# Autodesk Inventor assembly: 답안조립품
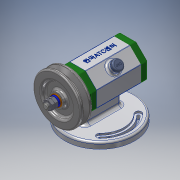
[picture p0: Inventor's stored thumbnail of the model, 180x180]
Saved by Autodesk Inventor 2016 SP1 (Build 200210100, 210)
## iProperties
Created: 2017-06
Part Number: 답안조립품
Material: 일반
Document SubType Name: Assembly
Designer: basic
Author: basic
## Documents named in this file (14)
- C:\Users\basic\Desktop\470608V1008\답안조립품.iam
- C:\Users\basic\Desktop\470608V1008\본체.ipt
- C:\Users\basic\Desktop\470608V1008\베어링 15 x 32 x 9.ipt
- C:\Users\basic\Desktop\470608V1008\뒤커버.ipt
- C:\Users\basic\Desktop\470608V1008\앞커버.ipt
- C:\Users\basic\Desktop\470608V1008\오일 실 15 25 7.ipt
- C:\Users\basic\Desktop\470608V1008\너트 M 8.ipt
- C:\Users\basic\Desktop\470608V1008\볼트 M4 x 12.ipt
- C:\Users\basic\Desktop\470608V1008\축.ipt
- C:\Users\basic\Desktop\470608V1008\키 3 x 3 x 12.ipt
- C:\Users\basic\Desktop\470608V1008\V벨트풀리.ipt
- C:\Users\basic\Desktop\470608V1008\와셔 8x17.ipt
- C:\Users\basic\Desktop\470608V1008\스프링와셔 8.ipt
- C:\Users\basic\Desktop\470608V1008\고무캡.ipt
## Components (2 placed, 2 different names)
1. V벨트풀리:1
2. 고무캡:1
